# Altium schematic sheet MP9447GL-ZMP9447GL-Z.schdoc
size 127 x 101 mm
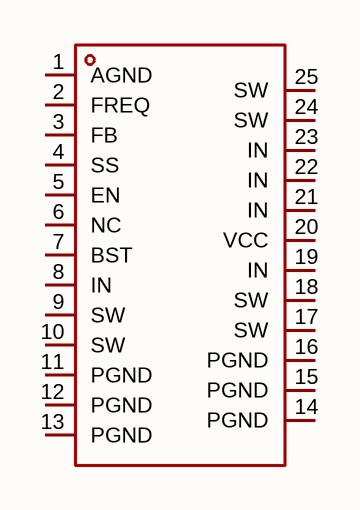
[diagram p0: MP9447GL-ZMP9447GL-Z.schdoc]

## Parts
U?  mp9447gl-z  [QFN-20_L4.0-W3.0_MP9447GL]  (value not drawn)

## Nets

Not connected (* = marked no-connect by the designer): U? 1(AGND) 2(FREQ) 3(FB) 4(SS) 5(EN) 6(NC) 7(BST) 8(IN) 9(SW) 10(SW) 11(PGND) 12(PGND) 13(PGND) 14(PGND) 15(PGND) 16(PGND) 17(SW) 18(SW) 19(IN) 20(VCC) 21(IN) 22(IN) 23(IN) 24(SW) 25(SW)

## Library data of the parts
U? = mp9447gl-z: 功能类型:降压型;工作电压:4.5V~36V;输出电压:800mV~32.4V;输出电流:5A;输出类型:可调;; Manufacturer: MPS(芯源); AddInBom: yes; ModelId: cee4ceeb648d4ebea9033b5d8a6adfa6; ModelTransform: 118.11,157.48,0,0,0,0,0,0,0; Function: 降压型; Output Current: 5A; Frequency - Switching: 200kHz~650kHz; Synchronous Rectifier: 是; Number of Outputs: 1; Topology: 降压式; Quiescent Current: 500uA; Switch tube (built-in/external): 内置; Output Type: 可调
